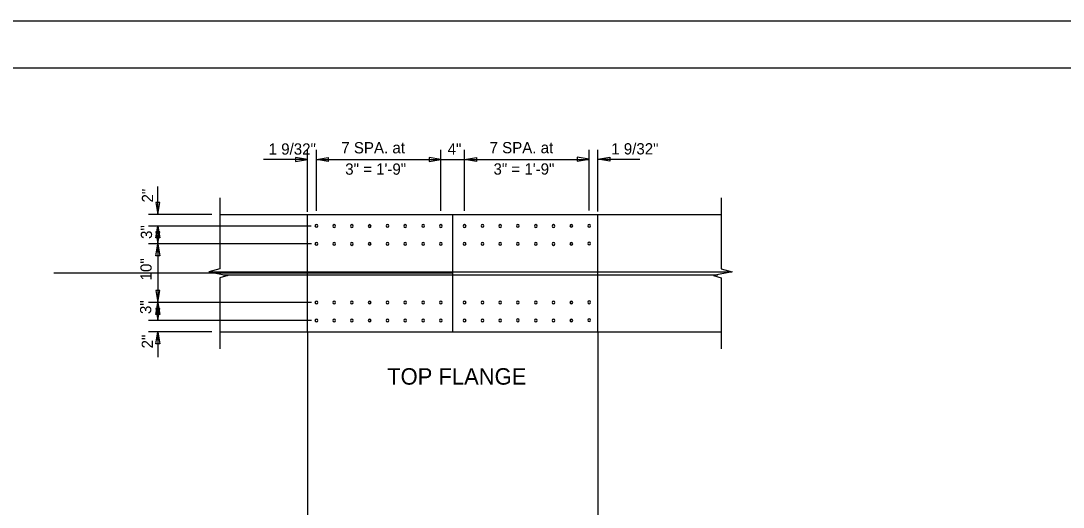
# Model space of a CAD drawing. Extents: x 4944 to 17449, y 3824 to 49087.
# Drawn here: x 13083 to 14149, y 34038 to 34535 of the extents above; entities that cross this region are included whole.
import ezdxf

# ---------------------------------------------------------------- set-up
doc = ezdxf.new("R2010")
doc.units = 0
for name, color, linetype in [('1', 7, 'Continuous'), ('2', 7, 'Continuous'), ('36_S_LINES', 7, 'Continuous'), ('3A', 7, 'Continuous'), ('7', 7, 'Continuous'), ('BEAM', 7, 'Continuous'), ('DIM', 7, 'Continuous'), ('Level 14', 7, 'Continuous'), ('Level 25', 7, 'Continuous')]:
    doc.layers.add(name, color=color, linetype=linetype)

msp = doc.modelspace()

# ---------------------------------------------------------------- linework, layer by layer
at = {"layer": '1'}
for centre, start, end in [((13664.3, 34325.4), 0, 180), ((13385.4, 34325.2), 0, 180), ((13385.4, 34325.2), 180, 0), ((13403.5, 34325.1), 0, 180), ((13403.5, 34325.1), 180, 0), ((13421.7, 34325.1), 0, 180), ((13421.7, 34325.1), 180, 0), ((13439.9, 34325.1), 0, 180), ((13439.9, 34325.1), 180, 0), ((13458.1, 34325.2), 0, 180), ((13458.1, 34325.2), 180, 0), ((13476.3, 34325.1), 0, 180), ((13476.3, 34325.1), 180, 0), ((13494.5, 34325.2), 0, 180), ((13494.5, 34325.2), 180, 0), ((13512.7, 34325.1), 0, 180), ((13512.7, 34325.1), 180, 0), ((13537, 34325.1), 0, 180), ((13537, 34325.1), 180, 0), ((13555.2, 34325.2), 0, 180), ((13555.2, 34325.2), 180, 0), ((13573.3, 34325.1), 0, 180), ((13573.3, 34325.1), 180, 0), ((13591.5, 34325.2), 0, 180), ((13591.5, 34325.2), 180, 0), ((13609.7, 34325.1), 0, 180), ((13609.7, 34325.1), 180, 0), ((13627.9, 34325.1), 0, 180), ((13627.9, 34325.1), 180, 0), ((13646.1, 34325.2), 0, 180), ((13646.1, 34325.2), 180, 0), ((13664.3, 34325.4), 180, 0), ((13385.4, 34306.9), 0, 180), ((13385.4, 34306.9), 180, 0), ((13403.5, 34306.9), 0, 180), ((13403.5, 34306.9), 180, 0), ((13421.7, 34306.8), 0, 180), ((13421.7, 34306.8), 180, 0), ((13439.9, 34306.9), 0, 180), ((13439.9, 34306.9), 180, 0), ((13458.1, 34306.9), 0, 180), ((13458.1, 34306.9), 180, 0), ((13476.3, 34306.9), 0, 180), ((13476.3, 34306.9), 180, 0), ((13494.5, 34306.9), 0, 180), ((13494.5, 34306.9), 180, 0), ((13512.7, 34306.9), 0, 180), ((13512.7, 34306.9), 180, 0), ((13537, 34306.9), 0, 180), ((13537, 34306.9), 180, 0), ((13555.2, 34306.9), 0, 180), ((13555.2, 34306.9), 180, 0), ((13573.3, 34306.9), 0, 180), ((13573.3, 34306.9), 180, 0), ((13591.5, 34306.9), 0, 180), ((13591.5, 34306.9), 180, 0), ((13609.7, 34306.9), 0, 180), ((13609.7, 34306.9), 180, 0), ((13627.9, 34306.8), 0, 180), ((13627.9, 34306.8), 180, 0), ((13646.1, 34307), 0, 180), ((13646.1, 34307), 180, 0), ((13664.3, 34307.2), 0, 180), ((13664.3, 34307.2), 180, 0), ((13385.4, 34246.9), 0, 180), ((13385.4, 34246.9), 180, 0), ((13403.5, 34246.9), 0, 180), ((13403.5, 34246.9), 180, 0), ((13421.7, 34246.9), 0, 180), ((13421.7, 34246.9), 180, 0), ((13439.9, 34247), 0, 180), ((13439.9, 34247), 180, 0), ((13458.1, 34246.9), 0, 180), ((13458.1, 34246.9), 180, 0), ((13476.3, 34247), 0, 180), ((13476.3, 34247), 180, 0), ((13494.5, 34246.9), 0, 180), ((13494.5, 34246.9), 180, 0), ((13512.7, 34247), 0, 180), ((13512.7, 34247), 180, 0), ((13537, 34247), 0, 180), ((13537, 34247), 180, 0), ((13555.2, 34246.9), 0, 180), ((13555.2, 34246.9), 180, 0), ((13573.3, 34247), 0, 180), ((13573.3, 34247), 180, 0), ((13591.5, 34247), 0, 180), ((13591.5, 34247), 180, 0), ((13609.7, 34247), 0, 180), ((13609.7, 34247), 180, 0), ((13627.9, 34246.9), 0, 180), ((13627.9, 34246.9), 180, 0), ((13646.1, 34247), 0, 180), ((13646.1, 34247), 180, 0), ((13664.3, 34247.2), 0, 180), ((13664.3, 34247.2), 180, 0), ((13385.4, 34228.7), 0, 180), ((13385.4, 34228.7), 180, 0), ((13403.5, 34228.6), 0, 180), ((13403.5, 34228.6), 180, 0), ((13421.7, 34228.7), 0, 180), ((13421.7, 34228.7), 180, 0), ((13439.9, 34228.7), 0, 180), ((13439.9, 34228.7), 180, 0), ((13458.1, 34228.7), 0, 180), ((13458.1, 34228.7), 180, 0), ((13476.3, 34228.7), 0, 180), ((13476.3, 34228.7), 180, 0), ((13494.5, 34228.7), 0, 180), ((13494.5, 34228.7), 180, 0), ((13512.7, 34228.7), 0, 180), ((13512.7, 34228.7), 180, 0), ((13537, 34228.7), 0, 180), ((13537, 34228.7), 180, 0), ((13555.2, 34228.7), 0, 180), ((13555.2, 34228.7), 180, 0), ((13573.3, 34228.7), 0, 180), ((13573.3, 34228.7), 180, 0), ((13591.5, 34228.8), 0, 180), ((13591.5, 34228.8), 180, 0), ((13609.7, 34228.7), 0, 180), ((13609.7, 34228.7), 180, 0), ((13627.9, 34228.7), 0, 180), ((13627.9, 34228.7), 180, 0), ((13646.1, 34228.7), 0, 180), ((13646.1, 34228.7), 180, 0), ((13664.3, 34228.9), 0, 180), ((13664.3, 34228.9), 180, 0)]:
    msp.add_arc(centre, 1.42, start, end, dxfattribs=at)
at = {"layer": '2'}
msp.add_line((13524.8, 34216.9), (13524.8, 34336.9), dxfattribs=at)
at = {"layer": '36_S_LINES'}
for p, q in [((13376.3, 34339.6), (13376.3, 34402.8)), ((13673.3, 34339.8), (13673.3, 34403)), ((13376.3, 34393.2), (13331.2, 34393.2)), ((13385.4, 34393.1), (13512.7, 34393.1)), ((13512.7, 34393.1), (13537.1, 34393.1)), ((13537.1, 34393.1), (13664.3, 34393.2)), ((13673.3, 34393.4), (13716, 34393.4)), ((13223.2, 34336.9), (13223.2, 34365.3)), ((13286.8, 34353.9), (13286.8, 34281.5)), ((13799.3, 34353.9), (13799.3, 34281.5)), ((13278.5, 34336.9), (13213.6, 34336.9)), ((13223.2, 34325.1), (13223.2, 34306.9)), ((13223.2, 34325.1), (13223.2, 34306.9)), ((13223.2, 34313), (13223.2, 34240.9)), ((13223.2, 34313), (13223.2, 34234.8)), ((13286.8, 34281.5), (13275.4, 34278.3)), ((13275.4, 34278.3), (13294.8, 34274.5)), ((13294.8, 34274.5), (13286.8, 34272.2)), ((13810.7, 34278.3), (13791.3, 34274.5)), ((13791.3, 34274.5), (13799.3, 34272.2)), ((13799.3, 34281.5), (13810.7, 34278.3)), ((13286.8, 34272.2), (13286.8, 34199.6)), ((13799.3, 34272.2), (13799.3, 34199.6)), ((13223.2, 34228.7), (13223.2, 34246.9)), ((13223.2, 34228.7), (13223.2, 34246.9)), ((13278.5, 34216.9), (13213.6, 34216.9)), ((13223.2, 34216.9), (13223.2, 34191.3))]:
    msp.add_line(p, q, dxfattribs=at)
for points in [[(13364.2, 34395.2), (13364.2, 34391.1), (13376.3, 34393.2)], [(13397.5, 34395.2), (13397.5, 34391.1), (13385.4, 34393.2)], [(13500.6, 34395.2), (13500.6, 34391.1), (13512.7, 34393.2)], [(13549.1, 34395.2), (13549.1, 34391.1), (13537, 34393.2)], [(13652.1, 34395.4), (13652.1, 34391.4), (13664.3, 34393.4)], [(13685.5, 34395.4), (13685.5, 34391.4), (13673.3, 34393.4)], [(13225.2, 34349), (13221.2, 34349), (13223.2, 34336.9)], [(13224.2, 34344.9), (13222.2, 34344.9), (13223.2, 34336.9)], [(13224.2, 34344.9), (13222.2, 34344.9), (13223.2, 34336.9)], [(13225.2, 34313), (13221.2, 34313), (13223.2, 34325.1)], [(13225.2, 34319.1), (13221.2, 34319.1), (13223.2, 34306.9)], [(13224.2, 34317.1), (13222.2, 34317.1), (13223.2, 34325.1)], [(13224.2, 34317.1), (13222.2, 34317.1), (13223.2, 34325.1)], [(13225.2, 34294.8), (13221.2, 34294.8), (13223.2, 34306.9)], [(13224.2, 34314.9), (13222.2, 34314.9), (13223.2, 34306.9)], [(13224.2, 34314.9), (13222.2, 34314.9), (13223.2, 34306.9)], [(13224.2, 34298.9), (13222.2, 34298.9), (13223.2, 34306.9)], [(13224.2, 34298.9), (13222.2, 34298.9), (13223.2, 34306.9)], [(13225.2, 34259.1), (13221.2, 34259.1), (13223.2, 34246.9)], [(13224.2, 34254.9), (13222.2, 34254.9), (13223.2, 34246.9)], [(13224.2, 34254.9), (13222.2, 34254.9), (13223.2, 34246.9)], [(13225.2, 34234.8), (13221.2, 34234.8), (13223.2, 34246.9)], [(13224.2, 34238.9), (13222.2, 34238.9), (13223.2, 34246.9)], [(13224.2, 34238.9), (13222.2, 34238.9), (13223.2, 34246.9)], [(13225.2, 34240.9), (13221.2, 34240.9), (13223.2, 34228.7)], [(13224.2, 34236.7), (13222.2, 34236.7), (13223.2, 34228.7)], [(13224.2, 34236.7), (13222.2, 34236.7), (13223.2, 34228.7)], [(13225.2, 34204.8), (13221.2, 34204.8), (13223.2, 34216.9)], [(13224.2, 34208.9), (13222.2, 34208.9), (13223.2, 34216.9)], [(13224.2, 34208.9), (13222.2, 34208.9), (13223.2, 34216.9)]]:
    msp.add_lwpolyline(points, close=True, dxfattribs=at)
at = {"layer": '3A'}
for p, q in [((13385.4, 34340.7), (13385.4, 34402.8)), ((13512.7, 34340.7), (13512.7, 34402.8)), ((13537, 34340.7), (13537, 34402.8)), ((13664.3, 34340.9), (13664.3, 34403)), ((13380, 34325.1), (13213.6, 34325.1)), ((13380.5, 34306.9), (13213.6, 34306.9)), ((13380.4, 34246.9), (13213.6, 34246.9)), ((13380.5, 34228.7), (13213.6, 34228.7))]:
    msp.add_line(p, q, dxfattribs=at)
at = {"layer": '7'}
for p, q in [((13275.9, 34278.4), (13810.1, 34278.4)), ((13290.2, 34275.4), (13795.9, 34275.4))]:
    msp.add_line(p, q, dxfattribs=at)
at = {"layer": 'DEFPOINTS'}
for p, q in [((13524.8, 34276.9), (13116.8, 34276.9)), ((13376.3, 34216.9), (13376.3, 33892.4)), ((13673.3, 34216.9), (13673.3, 33892.4))]:
    msp.add_line(p, q, dxfattribs=at)
at = {"layer": 'DIM'}
msp.add_lwpolyline([(12502.3, 34534.6), (15766.4, 34534.6), (15766.4, 32422.6), (12502.3, 32422.6)], close=True, dxfattribs=at)
at = {"layer": 'Level 14'}
msp.add_lwpolyline([(15713.6, 32470.6), (12689.5, 32470.6), (12689.5, 34486.6), (15713.6, 34486.6)], close=True, dxfattribs=at)
at = {"layer": 'Level 25'}
for p, q in [((13286.8, 34336.9), (13799.3, 34336.9)), ((13376.3, 34216.9), (13376.3, 34336.9)), ((13673.3, 34217.1), (13673.3, 34337.1)), ((13286.8, 34216.9), (13799.3, 34216.9))]:
    msp.add_line(p, q, dxfattribs=at)

# ---------------------------------------------------------------- texts
at = {"layer": '3A'}
for s, p in [('1 9/32"', (13336.6, 34398)), ('7 SPA. at', (13410.9, 34399.3)), ('4"', (13519.6, 34398)), ('7 SPA. at', (13562.5, 34399.4)), ('1 9/32"', (13686.9, 34398.2)), ('3" = 1\'-9"', (13414.9, 34377.5)), ('3" = 1\'-9"', (13566.5, 34377.6))]:
    msp.add_text(s, height=11.52, dxfattribs=at).set_placement(p)
for s, p in [('2"', (13218.5, 34349.1)), ('3"', (13217.4, 34311.9)), ('10"', (13217, 34269.6)), ('3"', (13216.6, 34235.2)), ('2"', (13218.3, 34200.1))]:
    msp.add_text(s, height=11.52, rotation=90, dxfattribs=at).set_placement(p)
at = {"layer": 'BEAM'}
msp.add_text('TOP FLANGE', height=16.8, dxfattribs=at).set_placement((13457.8, 34163.1))

doc.saveas('drawing.dxf')
